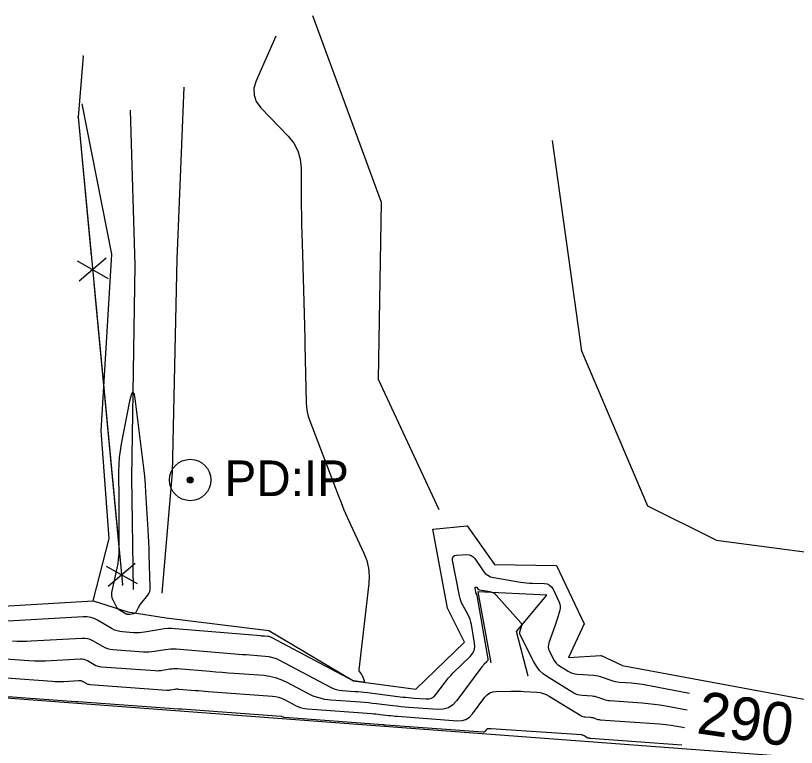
# Model space of a CAD drawing. Extents: x 1574966 to 1597594, y 720505 to 737840.
# Drawn here: x 1577690.4 to 1577800, y 724431.3 to 724534.1 of the extents above; entities that cross this region are included whole.
import ezdxf

# ---------------------------------------------------------------- set-up
doc = ezdxf.new("R2010")
doc.units = 0
for name, color, linetype in [('R_Contour Annot', 7, 'Continuous'), ('R_Contours', 7, 'Continuous'), ('S_BREAKLINE', 7, 'Continuous'), ('S_DITCHLINE', 7, 'Continuous'), ('S_FENCE', 7, 'Continuous'), ('S_IRON_PIN', 7, 'Continuous'), ('S_IRON_PIN_ANNOT', 7, 'Continuous'), ('S_MSC_PT_SYM', 7, 'Continuous'), ('S_STREAM', 7, 'Continuous')]:
    doc.layers.add(name, color=color, linetype=linetype)

msp = doc.modelspace()

# ---------------------------------------------------------------- linework, layer by layer
at = {"layer": 'R_Contours'}
for points in [[(1577726.93, 724531.18), (1577724.17, 724524.89), (1577723.87, 724523.86), (1577723.88, 724522.9), (1577724.2, 724521.99), (1577724.84, 724521.13), (1577728.67, 724517.13), (1577729.46, 724516.14), (1577730.02, 724515.06), (1577730.37, 724513.89), (1577730.49, 724512.63), (1577730.52, 724507.36), (1577730.54, 724506.04), (1577730.56, 724504.73), (1577730.58, 724503.41), (1577730.62, 724502.1), (1577730.95, 724490.53), (1577730.97, 724489.85), (1577730.99, 724489.16), (1577731.01, 724488.47), (1577731.03, 724487.78), (1577731.21, 724479.71), (1577731.25, 724479.06), (1577731.35, 724478.42), (1577731.5, 724477.79), (1577731.71, 724477.17), (1577735.68, 724466.72), (1577736.09, 724465.68), (1577736.51, 724464.64), (1577736.96, 724463.62), (1577737.42, 724462.6), (1577739.3, 724458.54), (1577739.7, 724457.52), (1577739.94, 724456.47), (1577740.04, 724455.39), (1577739.99, 724454.3), (1577738.58, 724442.16), (1577738.58, 724442.08), (1577738.6, 724442.01), (1577738.63, 724441.94), (1577738.67, 724441.88), (1577738.89, 724441.65), (1577738.95, 724441.59), (1577738.99, 724441.52), (1577739.03, 724441.45), (1577739.06, 724441.38), (1577739.33, 724440.7), (1577739.36, 724440.58), (1577739.34, 724440.5), (1577739.27, 724440.46), (1577739.15, 724440.46), (1577737.88, 724440.62), (1577737.86, 724440.62), (1577737.85, 724440.62), (1577737.83, 724440.62), (1577737.82, 724440.62), (1577737.82, 724440.62), (1577737.81, 724440.62), (1577737.81, 724440.63), (1577726.32, 724446.72), (1577726.21, 724446.77), (1577726.09, 724446.81), (1577725.97, 724446.84), (1577725.84, 724446.86), (1577725.34, 724446.89), (1577725.21, 724446.9), (1577725.09, 724446.91), (1577724.96, 724446.92), (1577724.83, 724446.93), (1577712.8, 724447.94), (1577712.29, 724447.96), (1577711.78, 724447.96), (1577711.27, 724447.92), (1577710.77, 724447.85), (1577708.5, 724447.46), (1577708.12, 724447.4), (1577707.74, 724447.37), (1577707.35, 724447.37), (1577706.96, 724447.38), (1577705.42, 724447.49), (1577705.03, 724447.54), (1577704.67, 724447.63), (1577704.31, 724447.77), (1577703.97, 724447.94), (1577701.9, 724449.15), (1577701.43, 724449.38), (1577700.95, 724449.54), (1577700.44, 724449.62), (1577699.92, 724449.62), (1577689.3, 724449)], [(1577690, 724446.24), (1577690.65, 724446.21), (1577691.29, 724446.19), (1577691.94, 724446.2), (1577692.59, 724446.23), (1577699.72, 724446.64), (1577700.11, 724446.64), (1577700.49, 724446.58), (1577700.85, 724446.46), (1577701.21, 724446.29), (1577702.59, 724445.48), (1577702.94, 724445.3), (1577703.3, 724445.16), (1577703.68, 724445.07), (1577704.07, 724445.02), (1577708.36, 724444.71), (1577708.75, 724444.7), (1577709.13, 724444.7), (1577709.52, 724444.73), (1577709.9, 724444.79), (1577711.42, 724445.05), (1577711.81, 724445.1), (1577712.19, 724445.13), (1577712.57, 724445.14), (1577712.96, 724445.12), (1577721.17, 724444.43), (1577721.71, 724444.39), (1577722.24, 724444.35), (1577722.77, 724444.31), (1577723.31, 724444.27), (1577725.45, 724444.11), (1577725.97, 724444.05), (1577726.48, 724443.93), (1577726.98, 724443.76), (1577727.46, 724443.53), (1577734.6, 724439.75), (1577735, 724439.56), (1577735.41, 724439.42), (1577735.83, 724439.32), (1577736.26, 724439.27), (1577738.03, 724439.14), (1577738.47, 724439.11), (1577738.91, 724439.07), (1577739.35, 724439.02), (1577739.79, 724438.97), (1577744.75, 724438.36), (1577745.16, 724438.32), (1577745.58, 724438.27), (1577745.99, 724438.24), (1577746.4, 724438.2), (1577748.06, 724438.08), (1577748.46, 724438.1), (1577748.81, 724438.2), (1577749.12, 724438.4), (1577749.39, 724438.69), (1577750.6, 724440.31), (1577750.89, 724440.69), (1577751.2, 724441.05), (1577751.52, 724441.4), (1577751.85, 724441.74), (1577754.22, 724444.04), (1577754.56, 724444.45), (1577754.77, 724444.91), (1577754.86, 724445.4), (1577754.83, 724445.93), (1577754.39, 724448.53), (1577754.31, 724448.88), (1577754.21, 724449.23), (1577754.08, 724449.57), (1577753.92, 724449.89), (1577753.22, 724451.18), (1577753.06, 724451.51), (1577752.92, 724451.85), (1577752.81, 724452.19), (1577752.73, 724452.55), (1577751.75, 724457.56), (1577751.73, 724457.87), (1577751.82, 724458.09), (1577752.02, 724458.23), (1577752.32, 724458.29), (1577753.74, 724458.36), (1577754.08, 724458.34), (1577754.38, 724458.24), (1577754.63, 724458.07), (1577754.86, 724457.81), (1577756.06, 724456.07), (1577756.35, 724455.72), (1577756.7, 724455.45), (1577757.09, 724455.25), (1577757.53, 724455.13), (1577761.27, 724454.49), (1577761.69, 724454.42), (1577762.11, 724454.38), (1577762.53, 724454.34), (1577762.96, 724454.33), (1577764.65, 724454.3), (1577765.05, 724454.24), (1577765.38, 724454.09), (1577765.65, 724453.85), (1577765.86, 724453.51), (1577766.7, 724451.68), (1577766.8, 724451.41), (1577766.85, 724451.13), (1577766.85, 724450.85), (1577766.79, 724450.57), (1577766.46, 724449.42), (1577766.38, 724449.14), (1577766.29, 724448.85), (1577766.19, 724448.57), (1577766.1, 724448.29), (1577765.27, 724445.99), (1577765.2, 724445.69), (1577765.18, 724445.39), (1577765.23, 724445.09), (1577765.35, 724444.8), (1577765.93, 724443.64), (1577766.09, 724443.36), (1577766.28, 724443.12), (1577766.51, 724442.9), (1577766.77, 724442.72), (1577767.99, 724441.98), (1577768.29, 724441.82), (1577768.6, 724441.7), (1577768.93, 724441.61), (1577769.27, 724441.57), (1577771.53, 724441.42), (1577771.85, 724441.39), (1577772.16, 724441.33), (1577772.47, 724441.26), (1577772.77, 724441.16), (1577773.97, 724440.72), (1577774.27, 724440.62), (1577774.58, 724440.55), (1577774.89, 724440.49), (1577775.2, 724440.46), (1577776.87, 724440.34), (1577777.25, 724440.31), (1577777.63, 724440.26), (1577778.01, 724440.21), (1577778.39, 724440.14), (1577785.01, 724438.89)], [(1577784.66, 724436.49), (1577781.67, 724437.06), (1577780.86, 724437.2), (1577780.03, 724437.32), (1577779.21, 724437.41), (1577778.38, 724437.48), (1577773.84, 724437.81), (1577773.62, 724437.83), (1577773.41, 724437.87), (1577773.2, 724437.92), (1577772.99, 724437.99), (1577772.18, 724438.29), (1577771.97, 724438.36), (1577771.76, 724438.41), (1577771.55, 724438.45), (1577771.33, 724438.47), (1577769.93, 724438.56), (1577769.63, 724438.6), (1577769.34, 724438.67), (1577769.06, 724438.78), (1577768.79, 724438.92), (1577765.1, 724441.17), (1577764.49, 724441.6), (1577763.96, 724442.1), (1577763.51, 724442.67), (1577763.14, 724443.31), (1577761.25, 724447.08), (1577761.2, 724447.22), (1577761.17, 724447.36), (1577761.18, 724447.51), (1577761.22, 724447.66), (1577761.43, 724448.25), (1577761.46, 724448.4), (1577761.46, 724448.53), (1577761.41, 724448.66), (1577761.33, 724448.79), (1577757.94, 724452.61), (1577757.75, 724452.8), (1577757.54, 724452.94), (1577757.3, 724453.05), (1577757.04, 724453.11), (1577755.54, 724453.37), (1577755.49, 724453.39), (1577755.44, 724453.41), (1577755.4, 724453.44), (1577755.37, 724453.48), (1577755.23, 724453.69), (1577755.2, 724453.72), (1577755.17, 724453.74), (1577755.14, 724453.75), (1577755.1, 724453.75), (1577754.93, 724453.74), (1577754.9, 724453.73), (1577754.87, 724453.72), (1577754.86, 724453.69), (1577754.86, 724453.66), (1577754.98, 724453.07), (1577754.99, 724453.03), (1577755, 724452.99), (1577755.02, 724452.95), (1577755.04, 724452.91), (1577755.12, 724452.76), (1577755.14, 724452.72), (1577755.15, 724452.68), (1577755.16, 724452.64), (1577755.17, 724452.6), (1577756.69, 724443.72), (1577756.7, 724443.6), (1577756.68, 724443.49), (1577756.63, 724443.39), (1577756.55, 724443.3), (1577756.2, 724442.95), (1577756.11, 724442.86), (1577756.03, 724442.77), (1577755.95, 724442.68), (1577755.87, 724442.58), (1577752.35, 724437.86), (1577751.8, 724437.26), (1577751.16, 724436.85), (1577750.43, 724436.64), (1577749.62, 724436.6), (1577745.62, 724436.9), (1577745.05, 724436.94), (1577744.49, 724437), (1577743.92, 724437.05), (1577743.35, 724437.12), (1577741.09, 724437.4), (1577740.52, 724437.46), (1577739.95, 724437.52), (1577739.39, 724437.57), (1577738.82, 724437.62), (1577734.64, 724437.92), (1577733.8, 724438.03), (1577732.99, 724438.22), (1577732.2, 724438.49), (1577731.44, 724438.84), (1577728.43, 724440.44), (1577727.67, 724440.79), (1577726.88, 724441.07), (1577726.07, 724441.25), (1577725.24, 724441.36), (1577721.09, 724441.65), (1577720.24, 724441.72), (1577719.39, 724441.78), (1577718.54, 724441.85), (1577717.69, 724441.92), (1577713.12, 724442.3), (1577712.86, 724442.31), (1577712.6, 724442.31), (1577712.34, 724442.29), (1577712.08, 724442.25), (1577711.05, 724442.08), (1577710.79, 724442.04), (1577710.53, 724442.02), (1577710.27, 724442.01), (1577710.01, 724442.03), (1577702.45, 724442.57), (1577702.19, 724442.6), (1577701.93, 724442.67), (1577701.68, 724442.76), (1577701.45, 724442.88), (1577700.52, 724443.42), (1577700.28, 724443.54), (1577700.03, 724443.62), (1577699.78, 724443.66), (1577699.51, 724443.66), (1577695.39, 724443.42), (1577694.61, 724443.39), (1577693.83, 724443.38), (1577693.05, 724443.4), (1577692.28, 724443.44), (1577687.7, 724443.77)], [(1577686.51, 724441.22), (1577695.56, 724440.57), (1577695.97, 724440.55), (1577696.37, 724440.54), (1577696.77, 724440.54), (1577697.17, 724440.56), (1577699.31, 724440.68), (1577699.44, 724440.68), (1577699.58, 724440.66), (1577699.7, 724440.62), (1577699.83, 724440.56), (1577700.31, 724440.28), (1577700.43, 724440.22), (1577700.56, 724440.17), (1577700.69, 724440.14), (1577700.83, 724440.12), (1577711.66, 724439.34), (1577711.79, 724439.33), (1577711.93, 724439.33), (1577712.06, 724439.35), (1577712.2, 724439.36), (1577712.74, 724439.46), (1577712.87, 724439.48), (1577713, 724439.49), (1577713.14, 724439.49), (1577713.28, 724439.48), (1577715.66, 724439.28), (1577716.1, 724439.25), (1577716.55, 724439.21), (1577716.99, 724439.18), (1577717.43, 724439.14), (1577726.46, 724438.5), (1577726.9, 724438.44), (1577727.32, 724438.34), (1577727.74, 724438.2), (1577728.14, 724438.01), (1577729.72, 724437.18), (1577730.12, 724436.99), (1577730.53, 724436.85), (1577730.95, 724436.75), (1577731.39, 724436.69), (1577740.4, 724436.03), (1577740.7, 724436.01), (1577741, 724435.98), (1577741.3, 724435.95), (1577741.6, 724435.92), (1577742.8, 724435.77), (1577743.1, 724435.74), (1577743.4, 724435.71), (1577743.7, 724435.68), (1577744, 724435.65), (1577752.46, 724435.03), (1577753.08, 724435.06), (1577753.63, 724435.22), (1577754.12, 724435.53), (1577754.54, 724435.98), (1577756.29, 724438.33), (1577756.61, 724438.68), (1577756.98, 724438.93), (1577757.41, 724439.09), (1577757.88, 724439.15), (1577759.95, 724439.2), (1577760.4, 724439.2), (1577760.86, 724439.2), (1577761.32, 724439.18), (1577761.77, 724439.15), (1577763.59, 724439.03), (1577764.04, 724438.97), (1577764.47, 724438.86), (1577764.89, 724438.7), (1577765.29, 724438.49), (1577769.77, 724435.76), (1577769.91, 724435.68), (1577770.06, 724435.62), (1577770.22, 724435.59), (1577770.38, 724435.57), (1577771.13, 724435.52), (1577771.25, 724435.5), (1577771.36, 724435.48), (1577771.47, 724435.46), (1577771.58, 724435.42), (1577772.02, 724435.26), (1577772.13, 724435.22), (1577772.24, 724435.2), (1577772.36, 724435.18), (1577772.47, 724435.16), (1577780.8, 724434.57), (1577781.62, 724434.49), (1577782.44, 724434.4), (1577783.25, 724434.28), (1577784.07, 724434.14), (1577784.32, 724434.09)], [(1577783.95, 724431.59), (1577771.11, 724432.52), (1577771.09, 724432.52), (1577771.08, 724432.52), (1577771.06, 724432.52), (1577771.05, 724432.53), (1577770.99, 724432.55), (1577770.97, 724432.55), (1577770.96, 724432.56), (1577770.94, 724432.56), (1577770.93, 724432.56), (1577770.83, 724432.57), (1577770.81, 724432.57), (1577770.79, 724432.58), (1577770.77, 724432.58), (1577770.75, 724432.6), (1577770.23, 724432.91), (1577770.14, 724432.96), (1577770.04, 724433), (1577769.94, 724433.02), (1577769.83, 724433.04), (1577757.18, 724433.9), (1577757.12, 724433.91), (1577757.06, 724433.91), (1577757, 724433.91), (1577756.94, 724433.91), (1577756.7, 724433.9), (1577756.64, 724433.9), (1577756.59, 724433.88), (1577756.54, 724433.85), (1577756.51, 724433.81), (1577756.29, 724433.52), (1577756.24, 724433.47), (1577756.19, 724433.43), (1577756.12, 724433.41), (1577756.04, 724433.41), (1577742.37, 724434.41), (1577742.34, 724434.41), (1577742.3, 724434.42), (1577742.27, 724434.42), (1577742.24, 724434.42), (1577742.11, 724434.44), (1577742.08, 724434.44), (1577742.05, 724434.45), (1577742.01, 724434.45), (1577741.98, 724434.45), (1577728.15, 724435.47), (1577728.11, 724435.47), (1577728.07, 724435.48), (1577728.03, 724435.49), (1577727.99, 724435.51), (1577727.84, 724435.59), (1577727.8, 724435.61), (1577727.76, 724435.62), (1577727.72, 724435.63), (1577727.68, 724435.64), (1577713.77, 724436.63), (1577713.73, 724436.64), (1577713.7, 724436.64), (1577713.66, 724436.64), (1577713.63, 724436.65), (1577713.43, 724436.66), (1577713.42, 724436.66), (1577713.41, 724436.66), (1577713.4, 724436.66), (1577713.39, 724436.66), (1577713.35, 724436.65), (1577713.34, 724436.65), (1577713.33, 724436.65), (1577713.31, 724436.65), (1577713.3, 724436.65), (1577699.2, 724437.67), (1577699.19, 724437.67), (1577699.18, 724437.67), (1577699.18, 724437.67), (1577699.17, 724437.68), (1577699.14, 724437.7), (1577699.13, 724437.7), (1577699.12, 724437.7), (1577699.11, 724437.7), (1577699.1, 724437.7), (1577698.96, 724437.7), (1577698.93, 724437.69), (1577698.91, 724437.69), (1577698.88, 724437.69), (1577698.85, 724437.7), (1577684.82, 724438.71)]]:
    msp.add_lwpolyline(points, dxfattribs=at)
msp.add_lwpolyline([(1577705.97, 724450.04), (1577706.01, 724450.03), (1577706.05, 724450.02), (1577706.09, 724450.01), (1577706.26, 724450), (1577706.3, 724450), (1577706.34, 724450), (1577706.38, 724450), (1577706.43, 724450.01), (1577707.03, 724450.11), (1577707.14, 724450.14), (1577707.23, 724450.19), (1577707.31, 724450.27), (1577707.37, 724450.36), (1577707.67, 724450.95), (1577707.74, 724451.08), (1577707.82, 724451.2), (1577707.9, 724451.33), (1577707.99, 724451.44), (1577708.96, 724452.67), (1577709.12, 724452.92), (1577709.24, 724453.19), (1577709.3, 724453.47), (1577709.32, 724453.77), (1577709.17, 724458.37), (1577709.14, 724459.24), (1577709.1, 724460.11), (1577709.06, 724460.98), (1577709.01, 724461.85), (1577708.71, 724467.07), (1577708.63, 724468.22), (1577708.54, 724469.38), (1577708.42, 724470.53), (1577708.29, 724471.69), (1577707.26, 724479.9), (1577707.08, 724480.9), (1577706.88, 724481.24), (1577706.66, 724480.92), (1577706.41, 724479.93), (1577705.23, 724473.9), (1577705.07, 724472.95), (1577704.96, 724472), (1577704.89, 724471.04), (1577704.87, 724470.07), (1577704.9, 724465.9), (1577704.91, 724465.08), (1577704.91, 724464.27), (1577704.91, 724463.46), (1577704.91, 724462.64), (1577704.9, 724459.09), (1577704.89, 724458.43), (1577704.83, 724457.77), (1577704.75, 724457.11), (1577704.62, 724456.46), (1577703.89, 724453.04), (1577703.86, 724452.8), (1577703.87, 724452.57), (1577703.92, 724452.34), (1577704.01, 724452.12), (1577704.49, 724451.15), (1577704.59, 724450.99), (1577704.7, 724450.84), (1577704.84, 724450.71), (1577705, 724450.61), (1577705.93, 724450.06)], close=True, dxfattribs=at)
at = {"layer": 'S_BREAKLINE'}
for p, q in [((1577713.11, 724499.85), (1577714.09, 724524.01)), ((1577703.94, 724500.57), (1577699.75, 724521.66)), ((1577707.19, 724499.01), (1577706.54, 724520.79)), ((1577769.91, 724486.93), (1577765.76, 724516.5)), ((1577702.42, 724475.73), (1577703.94, 724500.57)), ((1577712.46, 724469.83), (1577713.11, 724499.85)), ((1577706.72, 724469.17), (1577707.19, 724499.01)), ((1577779.15, 724465.15), (1577769.91, 724486.93)), ((1577703.56, 724460.61), (1577702.42, 724475.73)), ((1577706.94, 724453.44), (1577706.72, 724469.17)), ((1577711.01, 724452.95), (1577712.46, 724469.83)), ((1577788.76, 724460.38), (1577779.15, 724465.15)), ((1577701.32, 724451.87), (1577703.56, 724460.61)), ((1577788.76, 724460.38), (1577848.11, 724452.51)), ((1577764.98, 724452.64), (1577755.28, 724453.14)), ((1577755.28, 724453.14), (1577757.12, 724443.16)), ((1577760.71, 724447.56), (1577764.98, 724452.64)), ((1577701.32, 724451.87), (1577706.17, 724450.32)), ((1577762.35, 724441.29), (1577760.71, 724447.56)), ((1577775.57, 724442.79), (1577772.56, 724444.18))]:
    msp.add_line(p, q, dxfattribs=at)
at = {"layer": 'S_DITCHLINE'}
for p, q in [((1577732.1, 724534.06), (1577741.75, 724507.86)), ((1577741.75, 724507.86), (1577741.31, 724482.99)), ((1577741.31, 724482.99), (1577749.84, 724464.69))]:
    msp.add_line(p, q, dxfattribs=at)
at = {"layer": 'S_FENCE'}
for p, q in [((1577699.88, 724528.37), (1577699.18, 724519.8)), ((1577699.18, 724519.8), (1577705.43, 724454.11)), ((1577703.12, 724499.99), (1577699.32, 724496.75)), ((1577703.12, 724499.99), (1577699.32, 724496.75)), ((1577699.05, 724499.61), (1577703.4, 724497.14)), ((1577699.05, 724499.61), (1577703.4, 724497.14)), ((1577707.2, 724457.13), (1577703.39, 724453.89)), ((1577707.2, 724457.13), (1577703.39, 724453.89)), ((1577703.12, 724456.75), (1577707.47, 724454.28)), ((1577703.12, 724456.75), (1577707.47, 724454.28))]:
    msp.add_line(p, q, dxfattribs=at)
for points in [[(1577699.88, 724528.37), (1577699.18, 724519.8)], [(1577699.88, 724528.37), (1577699.18, 724519.8)], [(1577699.18, 724519.8), (1577701.04, 724500.32)], [(1577699.18, 724519.8), (1577701.04, 724500.32)], [(1577701.41, 724496.42), (1577705.11, 724457.46)], [(1577701.41, 724496.42), (1577705.11, 724457.46)]]:
    msp.add_lwpolyline(points, dxfattribs=at)
at = {"layer": 'S_IRON_PIN'}
for radius in [2.91, 2.91, 2.91, 0.411, 0.411, 0.411, 0.262, 0.262, 0.262, 0.212, 0.212, 0.212, 0.145, 0.145, 0.145, 0.0822, 0.0822, 0.0822, 0.0581, 0.0581, 0.0581]:
    msp.add_circle((1577714.92, 724468.84), radius, dxfattribs=at)
at = {"layer": 'S_MSC_PT_SYM'}
for points in [[(1577699.88, 724528.37), (1577699.88, 724528.42), (1577699.88, 724528.37), (1577699.83, 724528.37), (1577699.88, 724528.37), (1577699.88, 724528.32), (1577699.88, 724528.37), (1577699.93, 724528.37)], [(1577699.88, 724528.37), (1577699.88, 724528.42), (1577699.88, 724528.37), (1577699.83, 724528.37), (1577699.88, 724528.37), (1577699.88, 724528.32), (1577699.88, 724528.37), (1577699.93, 724528.37)], [(1577699.88, 724528.37), (1577699.88, 724528.42), (1577699.88, 724528.37), (1577699.83, 724528.37), (1577699.88, 724528.37), (1577699.88, 724528.32), (1577699.88, 724528.37), (1577699.93, 724528.37)], [(1577699.18, 724519.8), (1577699.18, 724519.85), (1577699.18, 724519.8), (1577699.13, 724519.8), (1577699.18, 724519.8), (1577699.18, 724519.75), (1577699.18, 724519.8), (1577699.23, 724519.8)], [(1577699.18, 724519.8), (1577699.18, 724519.85), (1577699.18, 724519.8), (1577699.13, 724519.8), (1577699.18, 724519.8), (1577699.18, 724519.75), (1577699.18, 724519.8), (1577699.23, 724519.8)], [(1577699.18, 724519.8), (1577699.18, 724519.85), (1577699.18, 724519.8), (1577699.13, 724519.8), (1577699.18, 724519.8), (1577699.18, 724519.75), (1577699.18, 724519.8), (1577699.23, 724519.8)], [(1577705.43, 724454.11), (1577705.43, 724454.17), (1577705.43, 724454.11), (1577705.38, 724454.11), (1577705.43, 724454.11), (1577705.43, 724454.07), (1577705.43, 724454.11), (1577705.48, 724454.11)], [(1577705.43, 724454.11), (1577705.43, 724454.17), (1577705.43, 724454.11), (1577705.38, 724454.11), (1577705.43, 724454.11), (1577705.43, 724454.07), (1577705.43, 724454.11), (1577705.48, 724454.11)], [(1577705.43, 724454.11), (1577705.43, 724454.17), (1577705.43, 724454.11), (1577705.38, 724454.11), (1577705.43, 724454.11), (1577705.43, 724454.07), (1577705.43, 724454.11), (1577705.48, 724454.11)]]:
    msp.add_lwpolyline(points, dxfattribs=at)
at = {"layer": 'S_STREAM'}
for p, q in [((1577748.99, 724461.92), (1577753.82, 724462.42)), ((1577751.03, 724450.83), (1577748.99, 724461.92)), ((1577753.82, 724462.42), (1577757.64, 724456.99)), ((1577757.64, 724456.99), (1577766.32, 724456.84)), ((1577766.32, 724456.84), (1577770.23, 724448.65)), ((1577686.9, 724451.03), (1577701.32, 724451.87)), ((1577753.44, 724446.08), (1577751.03, 724450.83)), ((1577706.17, 724450.32), (1577711.57, 724449.49)), ((1577711.57, 724449.49), (1577725.97, 724447.71)), ((1577770.23, 724448.65), (1577768.02, 724443.89)), ((1577725.97, 724447.71), (1577737.85, 724440.64)), ((1577746.6, 724439.47), (1577753.44, 724446.08)), ((1577768.02, 724443.89), (1577772.56, 724444.18)), ((1577775.57, 724442.79), (1577820.39, 724434.47)), ((1577737.85, 724440.64), (1577746.6, 724439.47)), ((1577684.72, 724438.57), (1577799.62, 724429.96))]:
    msp.add_line(p, q, dxfattribs=at)

# ---------------------------------------------------------------- texts
at = {"layer": 'R_Contour Annot'}
msp.add_text('290', height=6, rotation=351.7427, dxfattribs=at).set_placement((1577785.87, 724433.29))
at = {"layer": 'S_IRON_PIN_ANNOT'}
msp.add_text('PD:IP', height=5, dxfattribs=at).set_placement((1577719.74, 724466.58))

doc.saveas('drawing.dxf')
